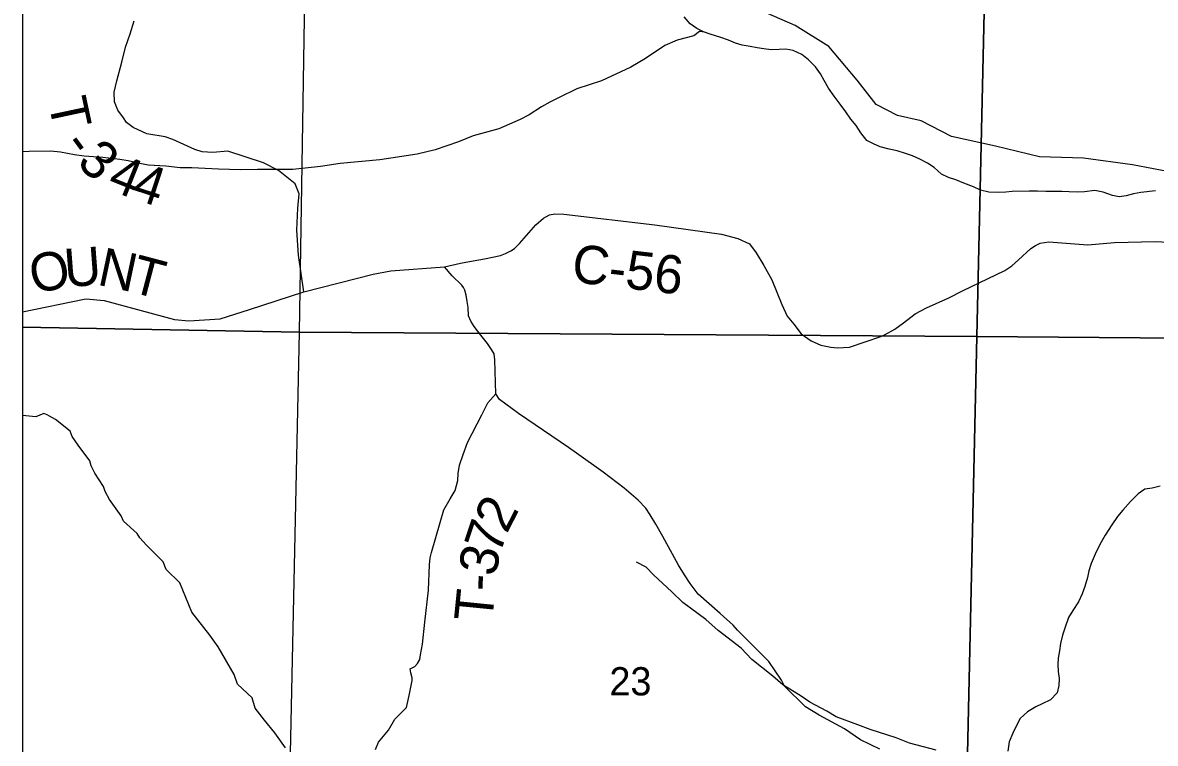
# Model space of a CAD drawing. Extents: x 2.1 to 8.9, y 14.1 to 20.9.
# Drawn here: x 2.1 to 3.78, y 17.519 to 18.588 of the extents above; entities that cross this region are included whole.
import ezdxf

# ---------------------------------------------------------------- set-up
doc = ezdxf.new("R2010")
doc.units = 0
for name, color, linetype in [('Default', 7, 'Continuous'), ('GM_X_City_Street', 7, 'Continuous'), ('GM_X_County_Road_Text', 7, 'Continuous'), ('GM_X_Interchange_Ramps', 7, 'Continuous'), ('GM_X_Minor_River', 7, 'Continuous'), ('GM_X_Minor_River_Text', 7, 'Continuous'), ('GM_X_State_Shield', 7, 'Continuous'), ('SH_Cut_Line', 7, 'Continuous'), ('SH_Data', 7, 'Continuous'), ('TX_P_Misc', 7, 'Continuous')]:
    doc.layers.add(name, color=color, linetype=linetype)

msp = doc.modelspace()

# ---------------------------------------------------------------- linework, layer by layer
at = {"layer": 'Default'}
for p, q in [((2.1, 19.1502), (2.1, 14.1)), ((2.1, 19.1493), (2.1, 18.1363)), ((2.5107, 18.1291), (2.5274, 19.148)), ((2.1, 18.1363), (2.1, 17.1299)), ((2.5107, 18.1291), (2.1, 18.1363)), ((2.1, 18.1363), (2.5107, 18.1291)), ((2.4891, 17.1265), (2.5107, 18.1291))]:
    msp.add_line(p, q, dxfattribs=at)
at = {"layer": 'GM_X_City_Street'}
for p, q in [((3.2459, 18.5838), (3.1811, 18.6124)), ((2.2597, 18.5716), (2.2652, 18.5909)), ((2.2526, 18.5518), (2.2597, 18.5716)), ((3.2961, 18.5526), (3.2459, 18.5838)), ((2.247, 18.5298), (2.2526, 18.5518)), ((3.338, 18.5031), (3.2961, 18.5526)), ((2.2396, 18.5019), (2.247, 18.5298)), ((2.2356, 18.4849), (2.2396, 18.5019)), ((3.366, 18.4668), (3.338, 18.5031)), ((2.2362, 18.4709), (2.2356, 18.4849)), ((2.241, 18.4585), (2.2362, 18.4709)), ((2.2494, 18.447), (2.241, 18.4585)), ((3.3981, 18.4507), (3.366, 18.4668)), ((3.4329, 18.4427), (3.3981, 18.4507)), ((2.2543, 18.4403), (2.2494, 18.447)), ((2.2638, 18.4325), (2.2543, 18.4403)), ((3.4778, 18.4193), (3.4329, 18.4427)), ((2.2841, 18.4232), (2.2638, 18.4325)), ((2.3114, 18.4186), (2.2841, 18.4232)), ((2.3227, 18.4149), (2.3114, 18.4186)), ((3.5431, 18.4051), (3.4778, 18.4193)), ((2.3556, 18.4), (2.3227, 18.4149)), ((3.6085, 18.3894), (3.5431, 18.4051)), ((2.3665, 18.3967), (2.3556, 18.4)), ((2.3819, 18.3957), (2.3665, 18.3967)), ((2.4046, 18.3976), (2.3819, 18.3957)), ((2.4571, 18.3801), (2.4046, 18.3976)), ((3.6736, 18.3873), (3.6085, 18.3894)), ((3.7467, 18.3772), (3.6736, 18.3873)), ((2.4798, 18.3688), (2.4571, 18.3801)), ((2.5044, 18.3489), (2.4798, 18.3688)), ((3.8087, 18.3652), (3.7467, 18.3772)), ((2.5101, 18.3342), (2.5044, 18.3489)), ((2.5082, 18.313), (2.5101, 18.3342)), ((2.5068, 18.2803), (2.5082, 18.313)), ((2.5092, 18.2434), (2.5068, 18.2803)), ((2.5172, 18.189), (2.5092, 18.2434)), ((2.7373, 18.2124), (2.7258, 18.2259)), ((2.7515, 18.1987), (2.7373, 18.2124)), ((2.7538, 18.1954), (2.7515, 18.1987)), ((2.7559, 18.1915), (2.7538, 18.1954)), ((2.7581, 18.1837), (2.7559, 18.1915)), ((2.7596, 18.1743), (2.7581, 18.1837)), ((2.7608, 18.1656), (2.7596, 18.1743)), ((2.7616, 18.1534), (2.7608, 18.1656)), ((2.7647, 18.1453), (2.7616, 18.1534)), ((2.7697, 18.1373), (2.7647, 18.1453)), ((2.7797, 18.1244), (2.7697, 18.1373)), ((2.7894, 18.1122), (2.7797, 18.1244)), ((2.7954, 18.1033), (2.7894, 18.1122)), ((2.7996, 18.0968), (2.7954, 18.1033)), ((2.8006, 18.0881), (2.7996, 18.0968)), ((2.8018, 18.0376), (2.8006, 18.0881)), ((2.7903, 18.0244), (2.8018, 18.0376)), ((2.8076, 18.0291), (2.8018, 18.0376)), ((2.7811, 18.0065), (2.7903, 18.0244)), ((2.8354, 18.0086), (2.8076, 18.0291)), ((2.7601, 17.9653), (2.7811, 18.0065)), ((2.9096, 17.9581), (2.8354, 18.0086)), ((2.7536, 17.9474), (2.7601, 17.9653)), ((2.7483, 17.9319), (2.7536, 17.9474)), ((2.9217, 17.9495), (2.9096, 17.9581)), ((2.9613, 17.9213), (2.9217, 17.9495)), ((2.7463, 17.9193), (2.7483, 17.9319)), ((2.7458, 17.9091), (2.7463, 17.9193)), ((2.9922, 17.8974), (2.9613, 17.9213)), ((2.7414, 17.8944), (2.7458, 17.9091)), ((3.0129, 17.8797), (2.9922, 17.8974)), ((2.7247, 17.8657), (2.734, 17.8818)), ((2.734, 17.8818), (2.7414, 17.8944)), ((3.0245, 17.8681), (3.0129, 17.8797)), ((2.7194, 17.8465), (2.7247, 17.8657)), ((3.0307, 17.8581), (3.0245, 17.8681)), ((2.7066, 17.8024), (2.7194, 17.8465)), ((3.0394, 17.8442), (3.0307, 17.8581)), ((3.0498, 17.8258), (3.0394, 17.8442)), ((3.064, 17.7998), (3.0498, 17.8258)), ((2.7044, 17.7945), (2.7066, 17.8024)), ((3.0728, 17.7832), (3.064, 17.7998)), ((2.7023, 17.7465), (2.7036, 17.7837)), ((2.7036, 17.7837), (2.7044, 17.7945)), ((3.0817, 17.7688), (3.0728, 17.7832)), ((3.0901, 17.756), (3.0817, 17.7688)), ((2.6968, 17.6988), (2.7023, 17.7465)), ((3.1023, 17.7405), (3.0901, 17.756)), ((3.1347, 17.7116), (3.1023, 17.7405)), ((3.1539, 17.6943), (3.1347, 17.7116)), ((2.6931, 17.6662), (2.6968, 17.6988)), ((3.1607, 17.6869), (3.1539, 17.6943)), ((3.207, 17.6406), (3.1607, 17.6869)), ((2.6904, 17.6503), (2.6931, 17.6662)), ((2.6892, 17.6434), (2.6904, 17.6503)), ((2.6751, 17.6296), (2.6817, 17.6331)), ((2.6761, 17.6236), (2.6751, 17.6296)), ((2.6817, 17.6331), (2.6859, 17.6373)), ((2.6859, 17.6373), (2.6892, 17.6434)), ((3.2258, 17.6127), (3.207, 17.6406)), ((2.6777, 17.6161), (2.6761, 17.6236)), ((2.677, 17.6075), (2.678, 17.6123)), ((2.678, 17.6123), (2.6777, 17.6161)), ((3.23, 17.6041), (3.2258, 17.6127)), ((2.6735, 17.5898), (2.677, 17.6075)), ((3.2613, 17.5733), (3.23, 17.6041)), ((2.6693, 17.5724), (2.6735, 17.5898)), ((2.6521, 17.5547), (2.6693, 17.5724)), ((3.2818, 17.5607), (3.2613, 17.5733)), ((3.3192, 17.5406), (3.2818, 17.5607)), ((2.6426, 17.5387), (2.6521, 17.5547)), ((2.6278, 17.521), (2.6426, 17.5387)), ((3.3432, 17.5241), (3.3192, 17.5406)), ((2.6233, 17.5099), (2.6278, 17.521)), ((3.3715, 17.5102), (3.3432, 17.5241))]:
    msp.add_line(p, q, dxfattribs=at)
at = {"layer": 'GM_X_Interchange_Ramps'}
for p, q in [((2.5107, 18.1291), (2.5274, 19.148)), ((3.5387, 19.1524), (3.5154, 18.1224)), ((3.5154, 18.1224), (3.5387, 19.1524)), ((2.4891, 17.1265), (2.5107, 18.1291)), ((3.5154, 18.1224), (2.5107, 18.1291)), ((2.5107, 18.1291), (3.5154, 18.1224)), ((3.5154, 18.1224), (3.4934, 17.1171)), ((3.4934, 17.1171), (3.5154, 18.1224)), ((4.5166, 18.1148), (3.5154, 18.1224)), ((3.5154, 18.1224), (4.5166, 18.1148))]:
    msp.add_line(p, q, dxfattribs=at)
at = {"layer": 'GM_X_State_Shield'}
for p, q in [((2.8727, 18.2981), (2.8818, 18.303)), ((2.8818, 18.303), (2.8897, 18.3045)), ((2.8897, 18.3045), (2.9028, 18.3041)), ((2.9028, 18.3041), (3.0381, 18.2883)), ((2.8373, 18.2606), (2.8615, 18.2883)), ((2.8615, 18.2883), (2.8727, 18.2981)), ((3.0381, 18.2883), (3.137, 18.2744)), ((3.137, 18.2744), (3.1612, 18.2679)), ((3.1612, 18.2679), (3.1783, 18.2599)), ((2.8165, 18.2456), (2.8244, 18.2496)), ((2.8244, 18.2496), (2.8297, 18.2532)), ((2.8297, 18.2532), (2.8373, 18.2606)), ((3.1783, 18.2599), (3.1883, 18.2467)), ((3.5775, 18.2366), (3.5956, 18.2532)), ((3.5956, 18.2532), (3.6027, 18.2576)), ((3.6027, 18.2576), (3.6094, 18.2609)), ((3.6094, 18.2609), (3.6226, 18.2629)), ((3.6226, 18.2629), (3.6801, 18.2585)), ((3.6801, 18.2585), (3.7197, 18.262)), ((3.7197, 18.262), (3.78, 18.2638)), ((3.78, 18.2638), (3.8103, 18.2619)), ((2.7494, 18.2313), (2.7683, 18.235)), ((2.7683, 18.235), (2.7854, 18.2378)), ((2.7854, 18.2378), (2.8091, 18.2429)), ((2.8091, 18.2429), (2.8165, 18.2456)), ((3.1883, 18.2467), (3.1998, 18.2278)), ((3.5676, 18.2275), (3.5775, 18.2366)), ((2.6199, 18.215), (2.6464, 18.2198)), ((2.6464, 18.2198), (2.7258, 18.2259)), ((2.7258, 18.2259), (2.7494, 18.2313)), ((3.1998, 18.2278), (3.2115, 18.2065)), ((3.4943, 18.1906), (3.5571, 18.2203)), ((3.5571, 18.2203), (3.5676, 18.2275)), ((2.5172, 18.189), (2.6199, 18.215)), ((3.2115, 18.2065), (3.2264, 18.1699)), ((2.4363, 18.1625), (2.5172, 18.189)), ((3.4738, 18.1802), (3.4943, 18.1906)), ((2.1, 18.159), (2.1911, 18.1781)), ((2.1911, 18.1781), (2.194, 18.1787)), ((2.194, 18.1787), (2.2211, 18.1758)), ((2.2211, 18.1758), (2.3254, 18.1476)), ((3.2264, 18.1699), (3.2343, 18.1527)), ((3.4242, 18.1561), (3.4409, 18.1653)), ((3.4409, 18.1653), (3.4738, 18.1802)), ((2.3467, 18.146), (2.3928, 18.1488)), ((2.3928, 18.1488), (2.4363, 18.1625)), ((3.2343, 18.1527), (3.2442, 18.1407)), ((3.4069, 18.1429), (3.4242, 18.1561)), ((2.3254, 18.1476), (2.3467, 18.146)), ((3.2442, 18.1407), (3.255, 18.1266)), ((3.3795, 18.1254), (3.3939, 18.1333)), ((3.3939, 18.1333), (3.4069, 18.1429)), ((3.255, 18.1266), (3.2697, 18.1161)), ((3.2697, 18.1161), (3.2843, 18.11)), ((3.3267, 18.1069), (3.3731, 18.1226)), ((3.3731, 18.1226), (3.3795, 18.1254)), ((3.2843, 18.11), (3.2991, 18.1066)), ((3.2991, 18.1066), (3.309, 18.1057)), ((3.309, 18.1057), (3.3267, 18.1069))]:
    msp.add_line(p, q, dxfattribs=at)
at = {"layer": 'SH_Cut_Line'}
msp.add_line((2.1, 20.9), (2.1, 14.1), dxfattribs=at)
at = {"layer": 'SH_Data'}
msp.add_line((2.1, 20.9), (2.1, 14.1), dxfattribs=at)
msp.add_line((2.1, 20.9), (2.1, 14.1), dxfattribs=at)
at = {"layer": 'TX_P_Misc'}
for p, q in [((3.0903, 18.5867), (3.0816, 18.5967)), ((3.1, 18.5794), (3.0903, 18.5867)), ((3.0956, 18.5686), (3.0711, 18.5622)), ((3.1042, 18.5753), (3.0956, 18.5686)), ((3.11, 18.5748), (3.1, 18.5794)), ((3.1114, 18.5743), (3.1042, 18.5753)), ((3.12, 18.5713), (3.11, 18.5748)), ((3.1358, 18.5661), (3.12, 18.5713)), ((3.0528, 18.5543), (3.024, 18.5348)), ((3.0711, 18.5622), (3.0528, 18.5543)), ((3.1469, 18.5622), (3.1358, 18.5661)), ((3.1577, 18.5576), (3.1469, 18.5622)), ((3.1673, 18.5549), (3.1577, 18.5576)), ((3.1791, 18.5526), (3.1673, 18.5549)), ((3.1898, 18.551), (3.1791, 18.5526)), ((3.024, 18.5348), (3.0023, 18.5222)), ((3.1998, 18.5494), (3.1898, 18.551)), ((3.2105, 18.5479), (3.1998, 18.5494)), ((3.2222, 18.5486), (3.2105, 18.5479)), ((3.2321, 18.5489), (3.2222, 18.5486)), ((3.2432, 18.547), (3.2321, 18.5489)), ((3.2559, 18.5409), (3.2432, 18.547)), ((3.2657, 18.5332), (3.2559, 18.5409)), ((3.0023, 18.5222), (2.9588, 18.5018)), ((3.2762, 18.5229), (3.2657, 18.5332)), ((3.2834, 18.5125), (3.2762, 18.5229)), ((2.9588, 18.5018), (2.922, 18.4901)), ((3.289, 18.5024), (3.2834, 18.5125)), ((3.2955, 18.4908), (3.289, 18.5024)), ((2.922, 18.4901), (2.8961, 18.4772)), ((3.3038, 18.4793), (3.2955, 18.4908)), ((2.8819, 18.4701), (2.8699, 18.4634)), ((2.8961, 18.4772), (2.8819, 18.4701)), ((3.3129, 18.4674), (3.3038, 18.4793)), ((3.3213, 18.4558), (3.3129, 18.4674)), ((2.8516, 18.4517), (2.8381, 18.4443)), ((2.8699, 18.4634), (2.8516, 18.4517)), ((3.3285, 18.445), (3.3213, 18.4558)), ((2.8381, 18.4443), (2.8066, 18.4308)), ((3.3364, 18.4354), (3.3285, 18.445)), ((3.3435, 18.4249), (3.3364, 18.4354)), ((2.7682, 18.4203), (2.7464, 18.4116)), ((2.8066, 18.4308), (2.7682, 18.4203)), ((3.3523, 18.4134), (3.3435, 18.4249)), ((2.7464, 18.4116), (2.7119, 18.3996)), ((3.3623, 18.4084), (3.3523, 18.4134)), ((3.3723, 18.4038), (3.3623, 18.4084)), ((3.3854, 18.4004), (3.3723, 18.4038)), ((3.3976, 18.3981), (3.3854, 18.4004)), ((2.1098, 18.3969), (2.1, 18.3965)), ((2.1415, 18.3974), (2.1098, 18.3969)), ((2.1559, 18.3961), (2.1415, 18.3974)), ((2.1768, 18.3919), (2.1559, 18.3961)), ((2.1912, 18.3903), (2.1768, 18.3919)), ((2.2188, 18.3881), (2.1912, 18.3903)), ((2.2442, 18.3854), (2.2188, 18.3881)), ((2.2567, 18.3834), (2.2442, 18.3854)), ((2.2738, 18.3791), (2.2567, 18.3834)), ((2.6297, 18.3849), (2.5712, 18.3794)), ((2.6855, 18.3931), (2.6297, 18.3849)), ((2.7119, 18.3996), (2.6855, 18.3931)), ((3.4095, 18.3943), (3.3976, 18.3981)), ((3.4199, 18.3908), (3.4095, 18.3943)), ((3.4311, 18.3858), (3.4199, 18.3908)), ((3.4423, 18.3797), (3.4311, 18.3858)), ((2.2863, 18.377), (2.2738, 18.3791)), ((2.3124, 18.3751), (2.2863, 18.377)), ((2.3336, 18.3728), (2.3124, 18.3751)), ((2.351, 18.3727), (2.3336, 18.3728)), ((2.3903, 18.3711), (2.351, 18.3727)), ((2.4232, 18.3701), (2.3903, 18.3711)), ((2.4482, 18.3702), (2.4232, 18.3701)), ((2.5007, 18.3706), (2.4482, 18.3702)), ((2.5418, 18.3747), (2.5007, 18.3706)), ((2.5712, 18.3794), (2.5418, 18.3747)), ((3.4524, 18.3732), (3.4423, 18.3797)), ((3.4629, 18.3636), (3.4524, 18.3732)), ((3.4733, 18.3586), (3.4629, 18.3636)), ((3.4845, 18.3548), (3.4733, 18.3586)), ((3.4964, 18.3502), (3.4845, 18.3548)), ((3.5107, 18.3446), (3.4964, 18.3502)), ((3.5211, 18.3396), (3.5107, 18.3446)), ((3.5333, 18.3369), (3.5211, 18.3396)), ((3.547, 18.3362), (3.5333, 18.3369)), ((3.5584, 18.3369), (3.547, 18.3362)), ((3.5679, 18.3376), (3.5584, 18.3369)), ((3.593, 18.3384), (3.5679, 18.3376)), ((3.6055, 18.338), (3.593, 18.3384)), ((3.6177, 18.3376), (3.6055, 18.338)), ((3.6302, 18.3377), (3.6177, 18.3376)), ((3.6417, 18.3376), (3.6302, 18.3377)), ((3.6527, 18.3372), (3.6417, 18.3376)), ((3.6649, 18.3365), (3.6527, 18.3372)), ((3.6755, 18.3372), (3.6649, 18.3365)), ((3.6906, 18.3392), (3.6755, 18.3372)), ((3.7029, 18.3369), (3.6906, 18.3392)), ((3.7167, 18.332), (3.7029, 18.3369)), ((3.7478, 18.3341), (3.7373, 18.3311)), ((3.7588, 18.3363), (3.7478, 18.3341)), ((3.7808, 18.3386), (3.7588, 18.3363)), ((3.7267, 18.33), (3.7167, 18.332)), ((3.7373, 18.3311), (3.7267, 18.33)), ((2.1197, 18.0034), (2.1, 18.0053)), ((2.1313, 18.0086), (2.1197, 18.0034)), ((2.1366, 18.0064), (2.1313, 18.0086)), ((2.1397, 18.0042), (2.1366, 18.0064)), ((2.1489, 17.9994), (2.1397, 18.0042)), ((2.1703, 17.9822), (2.1489, 17.9994)), ((2.1735, 17.9743), (2.1703, 17.9822)), ((2.1824, 17.9615), (2.1735, 17.9743)), ((2.1998, 17.9382), (2.1824, 17.9615)), ((2.2018, 17.9306), (2.1998, 17.9382)), ((2.2073, 17.9197), (2.2018, 17.9306)), ((2.2201, 17.9001), (2.2073, 17.9197)), ((2.2222, 17.8929), (2.2201, 17.9001)), ((3.7758, 17.8978), (3.7648, 17.8959)), ((3.7875, 17.9004), (3.7758, 17.8978)), ((2.2288, 17.8808), (2.2222, 17.8929)), ((2.2462, 17.8568), (2.2288, 17.8808)), ((3.7548, 17.8891), (3.7433, 17.8777)), ((3.7648, 17.8959), (3.7548, 17.8891)), ((3.7319, 17.8652), (3.7243, 17.8554)), ((3.7433, 17.8777), (3.7319, 17.8652)), ((2.2497, 17.8489), (2.2462, 17.8568)), ((2.2701, 17.8305), (2.2497, 17.8489)), ((3.7243, 17.8554), (3.7159, 17.843)), ((2.2736, 17.8238), (2.2701, 17.8305)), ((3.7159, 17.843), (3.7061, 17.8278)), ((2.2836, 17.8133), (2.2736, 17.8238)), ((2.3086, 17.7882), (2.2836, 17.8133)), ((3.6978, 17.8139), (3.691, 17.7996)), ((3.7061, 17.8278), (3.6978, 17.8139)), ((3.691, 17.7996), (3.6854, 17.7857)), ((2.313, 17.7772), (2.3086, 17.7882)), ((3.025, 17.7806), (3.0109, 17.7876)), ((3.0358, 17.7689), (3.025, 17.7806)), ((3.6854, 17.7857), (3.6819, 17.7749)), ((2.333, 17.757), (2.313, 17.7772)), ((3.0631, 17.7439), (3.0358, 17.7689)), ((3.6795, 17.765), (3.6757, 17.7519)), ((3.6819, 17.7749), (3.6795, 17.765)), ((2.3511, 17.7139), (2.333, 17.757)), ((3.6757, 17.7519), (3.6719, 17.7407)), ((3.0796, 17.7278), (3.0631, 17.7439)), ((3.6662, 17.7288), (3.6578, 17.7163)), ((3.6719, 17.7407), (3.6662, 17.7288)), ((2.3778, 17.6797), (2.3511, 17.7139)), ((3.1137, 17.7029), (3.0796, 17.7278)), ((3.6578, 17.7163), (3.6517, 17.7059)), ((3.1318, 17.6864), (3.1137, 17.7029)), ((3.6517, 17.7059), (3.6468, 17.6916)), ((2.3902, 17.6621), (2.3778, 17.6797)), ((3.1658, 17.6604), (3.1318, 17.6864)), ((3.6426, 17.6793), (3.6396, 17.667)), ((3.6468, 17.6916), (3.6426, 17.6793)), ((2.4136, 17.621), (2.3902, 17.6621)), ((3.6396, 17.667), (3.638, 17.6563)), ((3.182, 17.6435), (3.1658, 17.6604)), ((3.6364, 17.6456), (3.6356, 17.6361)), ((3.638, 17.6563), (3.6364, 17.6456)), ((3.2131, 17.6189), (3.182, 17.6435)), ((3.6356, 17.6361), (3.6363, 17.6258)), ((2.4187, 17.6066), (2.4136, 17.621)), ((3.2276, 17.6058), (3.2131, 17.6189)), ((3.6363, 17.6258), (3.6378, 17.6152)), ((3.6378, 17.6152), (3.6373, 17.6049)), ((2.4406, 17.5864), (2.4187, 17.6066)), ((3.2548, 17.5892), (3.2276, 17.6058)), ((3.6346, 17.5938), (3.6247, 17.5836)), ((3.6373, 17.6049), (3.6346, 17.5938)), ((2.445, 17.5713), (2.4406, 17.5864)), ((3.2678, 17.5802), (3.2548, 17.5892)), ((3.293, 17.5666), (3.2678, 17.5802)), ((3.6127, 17.5775), (3.6029, 17.573)), ((3.6247, 17.5836), (3.6127, 17.5775)), ((2.4586, 17.5536), (2.445, 17.5713)), ((3.3067, 17.5584), (3.293, 17.5666)), ((3.5906, 17.5658), (3.5799, 17.5559)), ((3.6029, 17.573), (3.5906, 17.5658)), ((2.474, 17.5344), (2.4586, 17.5536)), ((3.339, 17.5464), (3.3067, 17.5584)), ((3.3573, 17.5395), (3.339, 17.5464)), ((3.5738, 17.5443), (3.5688, 17.5343)), ((3.5799, 17.5559), (3.5738, 17.5443)), ((2.4899, 17.5123), (2.474, 17.5344)), ((3.3957, 17.5272), (3.3573, 17.5395)), ((3.4159, 17.5195), (3.3957, 17.5272)), ((3.5688, 17.5343), (3.5635, 17.5211)), ((3.455, 17.5091), (3.4159, 17.5195)), ((3.5635, 17.5211), (3.5616, 17.5074))]:
    msp.add_line(p, q, dxfattribs=at)

# ---------------------------------------------------------------- texts
at = {"layer": 'GM_X_County_Road_Text'}
msp.add_text('23', height=0.04186, rotation=0, dxfattribs=at).set_placement((2.9705, 17.5902))
at = {"layer": 'GM_X_Minor_River'}
for s, height, rotation, p in [('O', 0.0568, 12.0444, (2.1166, 18.1855)), ('U', 0.0568, 4.3389, (2.1635, 18.1956)), ('N', 0.0568, 348.0121, (2.2091, 18.1997)), ('C-56', 0.05682, 353.2897, (2.9128, 18.2038)), ('T', 0.0568, 345.2362, (2.2573, 18.1895))]:
    msp.add_text(s, height=height, rotation=rotation, dxfattribs=at).set_placement(p)
at = {"layer": 'GM_X_Minor_River_Text'}
for s, rotation, p in [('T', 282.0454, (2.1376, 18.4712)), ('-', 306.5459, (2.1573, 18.4057)), ('3', 316.7866, (2.1785, 18.3787)), ('4', 338.2372, (2.2235, 18.3423)), ('4', 341.8844, (2.2597, 18.328)), ('2', 62.8624, (2.818, 17.8288)), ('7', 71.4976, (2.8078, 17.7977)), ('3', 78.6115, (2.8014, 17.7652)), ('-', 88.1323, (2.8009, 17.7444)), ('T', 84.3295, (2.7964, 17.698))]:
    msp.add_text(s, height=0.0568, rotation=rotation, dxfattribs=at).set_placement(p)

doc.saveas('drawing.dxf')
